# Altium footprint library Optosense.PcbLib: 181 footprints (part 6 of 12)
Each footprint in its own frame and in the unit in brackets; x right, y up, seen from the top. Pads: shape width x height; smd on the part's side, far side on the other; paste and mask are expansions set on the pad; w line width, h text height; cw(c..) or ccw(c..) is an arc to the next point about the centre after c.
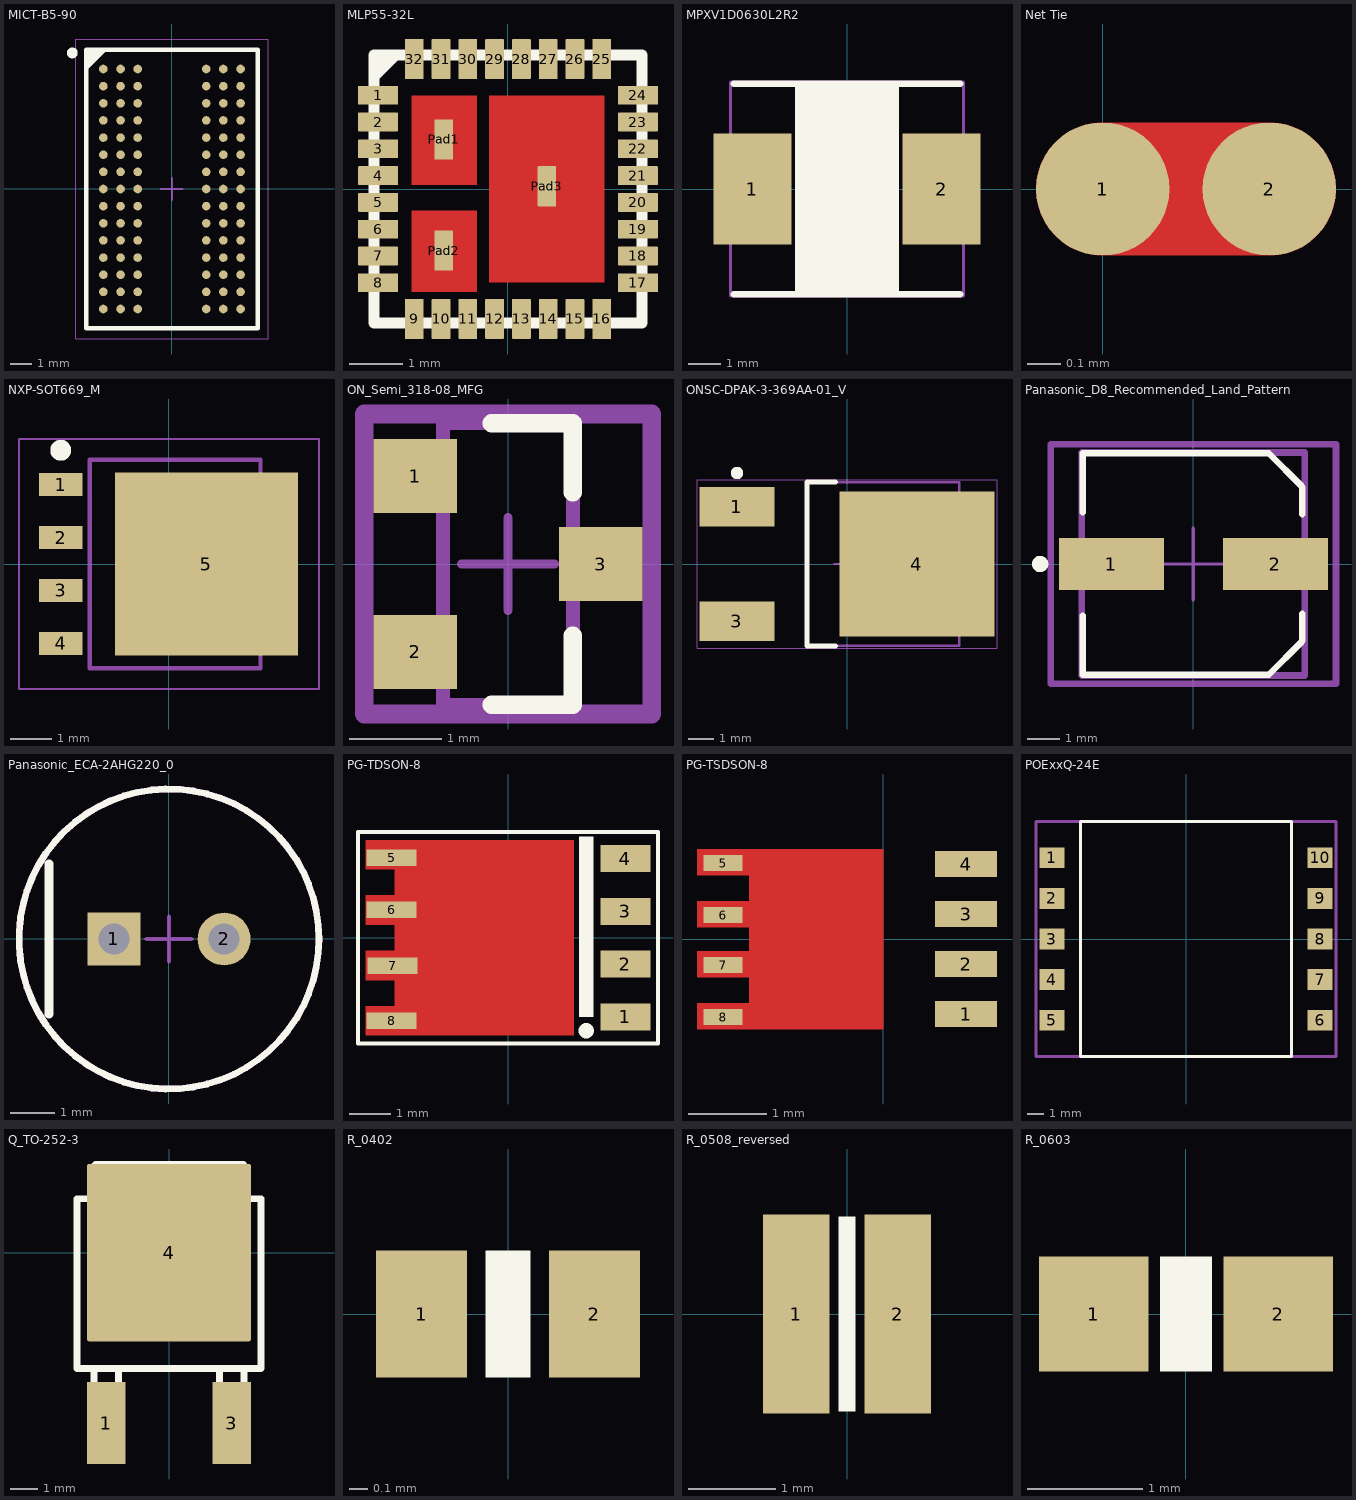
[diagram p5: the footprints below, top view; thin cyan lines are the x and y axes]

## MICT-B5-90 [mm] "BGA, 90-Balls, Body 13x8mm, Pitch 0.8mm"
pads (90):
  round 0.4 smd: A1(-3.2,5.6) A2(-2.4,5.6) A3(-1.6,5.6) A7(1.6,5.6) A8(2.4,5.6) A9(3.2,5.6) B1(-3.2,4.8) B2(-2.4,4.8) B3(-1.6,4.8) B7(1.6,4.8) B8(2.4,4.8) B9(3.2,4.8) C1(-3.2,4) C2(-2.4,4) C3(-1.6,4) C7(1.6,4) C8(2.4,4) C9(3.2,4) D1(-3.2,3.2) D2(-2.4,3.2) D3(-1.6,3.2) D7(1.6,3.2) D8(2.4,3.2) D9(3.2,3.2) E1(-3.2,2.4) E2(-2.4,2.4) E3(-1.6,2.4) E7(1.6,2.4) E8(2.4,2.4) E9(3.2,2.4) F1(-3.2,1.6) F2(-2.4,1.6) F3(-1.6,1.6) F7(1.6,1.6) F8(2.4,1.6) F9(3.2,1.6) G1(-3.2,0.8) G2(-2.4,0.8) G3(-1.6,0.8) G7(1.6,0.8) G8(2.4,0.8) G9(3.2,0.8) H1(-3.2,0) H2(-2.4,0) H3(-1.6,0) H7(1.6,0) H8(2.4,0) H9(3.2,0) J1(-3.2,-0.8) J2(-2.4,-0.8) J3(-1.6,-0.8) J7(1.6,-0.8) J8(2.4,-0.8) J9(3.2,-0.8) K1(-3.2,-1.6) K2(-2.4,-1.6) K3(-1.6,-1.6) K7(1.6,-1.6) K8(2.4,-1.6) K9(3.2,-1.6) L1(-3.2,-2.4) L2(-2.4,-2.4) L3(-1.6,-2.4) L7(1.6,-2.4) L8(2.4,-2.4) L9(3.2,-2.4) M1(-3.2,-3.2) M2(-2.4,-3.2) M3(-1.6,-3.2) M7(1.6,-3.2) M8(2.4,-3.2) M9(3.2,-3.2) N1(-3.2,-4) N2(-2.4,-4) N3(-1.6,-4) N7(1.6,-4) N8(2.4,-4) N9(3.2,-4) P1(-3.2,-4.8) P2(-2.4,-4.8) P3(-1.6,-4.8) P7(1.6,-4.8) P8(2.4,-4.8) P9(3.2,-4.8) R1(-3.2,-5.6) R2(-2.4,-5.6) R3(-1.6,-5.6) R7(1.6,-5.6) R8(2.4,-5.6) R9(3.2,-5.6)
Top Overlay:
  circle w0.25: c-4.65,6.35 r0.125
  region: -3.149,6.5 -4,5.649 -4,6.5
  lines w0.2: -4,5.649 -3.149,6.5 ; -4,-6.5 4,-6.5 4,6.5 -4,6.5 -4,-6.5
Mechanical 13:
  lines w0.1: -4,-6.5 4,-6.5 4,6.5 -4,6.5 -4,-6.5
Mechanical 15:
  lines w0.05: -4.5,-7 4.5,-7 4.5,7 -4.5,7 -4.5,-7
  lines w0.1: -0.5,0 0.5,0 ; 0,-0.5 0,0.5
3D body: height 0.3, standoff 0, extent -4,-6.5 4,6.5

## MLP55-32L [mm]
pads (35):
  rrect10% 0.75x0.35 smd: 1(-2.425,1.75) 2(-2.425,1.25) 3(-2.425,0.75) 4(-2.425,0.25) 5(-2.425,-0.25) 6(-2.425,-0.75) 7(-2.425,-1.25) 8(-2.425,-1.75) 17(2.425,-1.75) 18(2.425,-1.25) 19(2.425,-0.75) 20(2.425,-0.25) 21(2.425,0.25) 22(2.425,0.75) 23(2.425,1.25) 24(2.425,1.75)
  rrect10% 0.35x0.75 smd: 9(-1.75,-2.425) 10(-1.25,-2.425) 11(-0.75,-2.425) 12(-0.25,-2.425) 13(0.25,-2.425) 14(0.75,-2.425) 15(1.25,-2.425) 16(1.75,-2.425) 25(1.75,2.425) 26(1.25,2.425) 27(0.75,2.425) 28(0.25,2.425) 29(-0.25,2.425) 30(-0.75,2.425) 31(-1.25,2.425) 32(-1.75,2.425)
  rrect10% 0.35x0.75 smd paste+0 mask+0: Pad1(-1.2,0.925) Pad2(-1.2,-1.15) Pad3(0.725,0.05)
Top Layer:
  rectangle: -1.8,-1.925 -0.575,-0.4
  rectangle: -1.8,0.075 -0.575,1.75
  rectangle: -0.35,-1.75 1.8,1.75
Top Overlay:
  lines w0.2: -2.5,2.1 -2.1,2.5 ; -2.5,2.275 -2.275,2.5 ; -2.5,-2.5 2.5,-2.5 2.5,2.5 -2.5,2.5 -2.5,-2.5

## MPXV1D0630L2R2 [mil] "MPXV1D0630L2R2"
pads (2):
  rect 95x135 smd paste-7.87: 1(-115,0) 2(115,0)
Top Overlay:
  rectangle: -62.99,-127.95 62.99,127.95
  lines w7.87: -137.8,-127.95 137.8,-127.95 ; -137.8,127.95 137.8,127.95
Mechanical 15:
  lines w3.94: -141.73,-129.92 141.73,-129.92 141.73,129.92 -141.73,129.92 -141.73,-129.92
3D body "ASPI-0630HI.STEP": height 116.14, standoff -1.97, extent -141.73,-130.91 141.73,130.91

## Net Tie [mm]
pads (2):
  round 0.4 smd paste+0 mask+0: 1(0,0) 2(0.5,0)
Top Layer:
  lines w0.4: 0,0 0.5,0

## NXP-SOT669_M [mm] "DPAK, 4-Leads, Body 5x4.1mm, Pitch 1.27mm, IPC Low Density"
height 1.2
pads (5):
  rect 1.05x0.55 smd: 1(-2.6,1.905) 2(-2.6,0.635) 3(-2.6,-0.635) 4(-2.6,-1.905)
  rect 4.4x4.4 smd: 5(0.9,0)
Top Overlay:
  circle w0.25: c-2.6,2.73 r0.125
Mechanical 13:
  lines w0.1: -1.9,-2.5 -1.9,2.5 2.2,2.5 2.2,-2.5 -1.9,-2.5
Mechanical 15:
  lines w0.05: -3.6,-3 -3.6,3 3.6,3 3.6,-3 -3.6,-3
  lines w0.1: -0.5,0 0.5,0 ; 0,-0.5 0,0.5
3D body: height 1.2, standoff 0, extent -1.9,-2.5 2.2,2.5

## ON_Semi_318-08_MFG [mm]
pads (3):
  rect 0.9x0.8 smd paste+0 mask+0: 1(-1,0.95) 2(-1,-0.95) 3(1,0)
Top Overlay:
  lines w0.2: -0.175,-1.52 0.7,-1.52 0.7,-0.775 ; -0.175,1.52 0.7,1.52 0.7,0.775
Mechanical 10:
  lines w0.2: -1.55,-1.62 1.55,-1.62 1.55,1.62 -1.55,1.62 -1.55,-1.62
  text ".Designator" at 0,0 h1
Mechanical 12:
  lines w0.15: -0.7,-1.52 0.7,-1.52 0.7,1.52 -0.7,1.52 -0.7,-1.52
Mechanical 15:
  lines w0.1: -0.5,0 0.5,0 ; 0,-0.5 0,0.5
  lines w0.2: -1.55,-1.62 1.55,-1.62 1.55,1.62 -1.55,1.62 -1.55,-1.62
3D body "Trans_ON_Semi_NTR4170NT1G_eec.STEP": height 0.25, standoff 0, extent -1.55,-1.62 1.55,1.62

## ONSC-DPAK-3-369AA-01_V [mm] "DPAK, 3-Leads, Body 6.54x6.095mm, Pitch 2.29mm"
height 2.47
pads (3):
  rect 3x1.6 smd: 1(-4.4,2.29) 3(-4.4,-2.29)
  rect 6.2x5.8 smd: 4(2.8,0)
Top Overlay:
  circle w0.25: c-4.4,3.64 r0.125
  lines w0.2: -0.453,-3.27 -1.6,-3.27 -1.6,3.27 -0.453,3.27
Mechanical 13:
  lines w0.1: -1.6,-3.27 -1.6,3.27 4.495,3.27 4.495,-3.27 -1.6,-3.27
Mechanical 15:
  lines w0.05: 5.99,-3.37 -6,-3.37 -6,3.37 5.99,3.37 ; 6,-3.37 6,3.37
  lines w0.1: -0.5,0 0.5,0 ; 0,-0.5 0,0.5
3D body: height 2.47, standoff 0, extent -1.6,-3.27 4.495,3.27

## Panasonic_D8_Recommended_Land_Pattern [mm]
pads (2):
  rect 3.2x1.6 smd paste+0 mask+0: 1(-2.5,0) 2(2.5,0)
Top Overlay:
  circle w0.25: c-4.675,0 r0.125
  lines w0.2: -3.375,-3.375 -3.375,-1.575 ; -3.375,1.575 -3.375,3.375 2.225,3.375 ; -3.3,-3.375 2.3,-3.375 3.3,-2.375 ; 2.3,3.375 3.3,2.375 ; 3.325,-2.325 3.325,-1.525 ; 3.325,1.525 3.325,2.325
Mechanical 10:
  lines w0.2: -4.35,-3.65 -4.35,3.65 4.35,3.65 4.35,-3.65 -4.35,-3.65
  text ".Designator" at 0,0 h1
Mechanical 12:
  lines w0.2: -3.4,-3.4 -3.4,3.4 3.4,3.4 3.4,-3.4 -3.4,-3.4
Mechanical 15:
  lines w0.1: -1.095,0 1.095,0 ; 0,-1.095 0,1.095
  lines w0.2: -4.35,-3.65 -4.35,3.65 4.35,3.65 4.35,-3.65 -4.35,-3.65
3D body "Cap_Panasonic_EEE-FTH101XAP_eec.STEP": height 0.25, standoff 0, extent -4.35,-3.65 4.35,3.65

## Panasonic_ECA-2AHG220_0 [mm]
pads (2):
  rect 1.2x1.2 hole 0.7 paste-1000 mask+0: 1(-1.25,0)
  round 1.2 hole 0.7 paste-1000 mask+0: 2(1.25,0)
Top Overlay:
  circle w0.15: c0,0 r3.4
  lines w0.2: -2.72,-1.7 -2.72,1.7
Mechanical 10:
  text ".Designator" at 0,0 h1
Mechanical 12:
  circle w0.15: c0,0 r3.4
Mechanical 15:
  lines w0.1: -0.5,0 0.5,0 ; 0,-0.5 0,0.5
3D body "Cap_Panasonic_ECA-2AHG220_eec.STEP": height 12.29, standoff -16.91, extent -3.402,-3.408 3.391,3.392

## PG-TDSON-8 [mm]
pads (8):
  rect 1.2x0.65 smd: 1(2.825,-1.905) 2(2.825,-0.635) 3(2.825,0.635) 4(2.825,1.905)
  rect 1.2x0.4 smd mask+0: 5(-2.8,1.925) 6(-2.8,0.675) 7(-2.775,-0.675) 8(-2.8,-2)
Top Layer:
  region: -3.425,-2.35 1.575,-2.35 1.575,2.35 -3.425,2.35 -3.425,1.65 -2.725,1.65 -2.725,1.02 -3.425,1.02 -3.425,0.315 -2.725,0.315 -2.725,-0.315 -3.425,-0.315 -3.425,-1.02 -2.725,-1.02 -2.725,-1.65 -3.425,-1.65
Top Overlay:
  circle w0.254: c1.88,-2.235 r0.056
  rectangle: 1.702,-1.905 2.057,2.438
  lines w0.1: -3.607,-2.54 3.607,-2.54 3.607,2.54 -3.607,2.54 -3.607,-2.54
3D body "User Library-TDSON-8-1.step": height 1, standoff 0, extent -3.024,-2.675 3.126,2.675

## PG-TSDSON-8 [mil]
pads (8):
  rect 31x13 smd: 1(41.5,-37.5) 2(41.5,-12.5) 3(41.5,12.5) 4(41.5,37.5)
  rect 19.68x7.87 smd paste+0 mask+0: 5(-80,38) 6(-80,12) 7(-80,-13) 8(-80,-39)
Top Layer:
  region: 0,-45 -93,-45 -93,-32 -67,-32 -67,-19 -93,-19 -93,-6 -67,-6 -67,6 -93,6 -93,19 -67,19 -67,32 -93,32 -93,45 0,45

## POExxQ-24E [mm] "Coilcraft Flyback Transformer"
pads (10):
  rect 1.55x1.27 smd: 1(-8.268,5) 2(-8.268,2.5) 3(-8.268,0) 4(-8.268,-2.5) 5(-8.268,-5) 6(8.268,-5) 7(8.268,-2.5) 8(8.268,0) 9(8.268,2.5) 10(8.268,5)
Top Overlay:
  lines w0.2: -6.5,-7.25 -6.5,7.25 6.5,7.25 6.5,-7.25 -6.5,-7.25
Mechanical 15:
  lines w0.2: -9.25,-7.25 9.25,-7.25 9.25,7.25 -9.25,7.25 -9.25,-7.25
3D body "Coilcraft-POE51Q-XXX.STEP": height 13.87, standoff 0, extent -8.55,-7.251 8.45,7.249

## Q_TO-252-3 [mm]
pads (3):
  rect 1.4x3 smd: 1(-2.3,-6.25) 3(2.3,-6.25)
  rrect2% 6x6.5 smd: 4(0,0)
Top Overlay:
  lines w0.254: -2.75,-6.85 -2.75,-4.25 -2.75,-7.15 -1.85,-7.15 -1.85,-4.25 ; 1.85,-4.25 1.85,-7.15 2.75,-7.15 2.75,-4.25 ; -2.725,1.975 -2.725,3.2 -2.7,3.225 2.725,3.225 2.725,1.975 ; -2.725,1.975 -3.375,1.975 -3.375,-4.25 3.375,-4.25 3.375,1.975 2.725,1.975 ; -2.725,1.975 2.725,1.975

## R_0402 [mm]
pads (2):
  rect 0.5x0.7 smd: 1(-0.475,0) 2(0.475,0)
Top Overlay:
  rectangle: -0.125,-0.35 0.125,0.35
3D body "Resistor_0402.step": height 0.36, standoff 0.01, extent -0.508,-0.254 0.508,0.254

## R_0508_reversed [mil]
pads (2):
  rect 30x90 smd: 1(-23,0) 2(23,0)
Top Overlay:
  rectangle: -3.94,-44.29 3.94,44.29
3D body "User Library-RESC1220X07N.STEP": height 27.56, standoff 0, extent -26.58,-40.34 26.58,42.34

## R_0603 [mm]
pads (2):
  rect 0.95x1 smd: 1(-0.8,0) 2(0.8,0)
Top Overlay:
  rectangle: -0.225,-0.5 0.225,0.5
3D body "CircuitWorks-RESISTOR 0603.step": height 0.53, standoff 0.02, extent -0.8,-0.43 0.8,0.43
